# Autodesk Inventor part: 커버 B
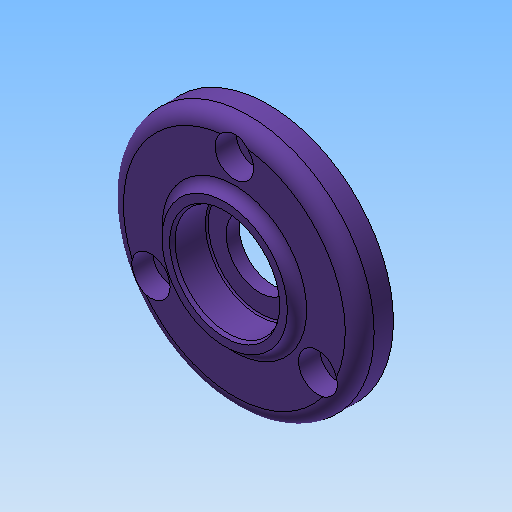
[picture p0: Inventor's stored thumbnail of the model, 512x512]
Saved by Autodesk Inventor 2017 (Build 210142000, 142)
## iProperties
Created: 2020-04
Part Number: 커버 B
Material: 알루미늄 6061
Document SubType Name: Modeling
Designer: mduedu
Density: 2.71 g/cm^3
Mass: 35.0669 g
Surface Area: 63.5386 cm^2
Volume: 12.9398 cm^3
Appearance: 보라색
Author: mduedu
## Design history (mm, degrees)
sketch "스케치1"
  geometry: C1 r 26 at (0, 0); 1 further point
  constraints: 1 centre point, 1 coincident
  dimensions: "d0" = 52 diameter of C1
extrude "돌출1" new body sketch "스케치1" distance "d1" = 7; taper "d2" = 0 deg
sketch "스케치6"
  geometry: C1 r 13 at (0, 0); 1 further point
  constraints: 1 centre point, 1 coincident
  dimensions: "d29" = 26 diameter of C1
extrude "돌출5" join sketch "스케치6" distance "d30" = 2; taper "d31" = 0 deg
fillet "모깎기2" dims "d7" = 3
fillet "모깎기4" dims "d33" = 2
sketch "스케치3" dims "d8" = 40
  geometry: 3 further points
  constraints: 2 vertical alignment, 1 coincident, 2 other
hole "구멍1" sketch "스케치3" at (0, 20) diameter "d9" = 4.5; stored, may be unused: countersink angle "d13" = 90 deg, drill point angle "d15" = 118 deg; dims "d10" = 6, "d11" = 8, "d12" = 4.4, "d14" = 8
sketch "스케치4"
  geometry: C1 r 14 at (0, 0); 1 further point
  constraints: 1 centre point, 1 coincident
  dimensions: "d19" = 28 diameter of C1
extrude "돌출3" join sketch "스케치4" distance "d20" = 4; taper "d21" = 0 deg
sketch "스케치5"
  geometry: C1 r 12 at (0, 0); 1 further point
  constraints: 1 centre point, 1 coincident
  dimensions: "d22" = 24 diameter of C1
extrude "돌출4" cut sketch "스케치5" distance "d23" = 3; taper "d24" = 0 deg
fillet "모깎기3" dims "d25" = 3
chamfer "모따기1" distance "d26" = 0.5; stored, may be unused: second distance "d27" = 2, angle "d28" = 45 deg
sketch "스케치7"
  geometry: 2 further points
  constraints: 1 coincident
hole "구멍2" sketch "스케치7" at (0, 0) diameter "d34" = 14; stored, may be unused: countersink angle "d38" = 90 deg, drill point angle "d40" = 118 deg; dims "d35" = 6, "d36" = 22, "d37" = 7.3, "d39" = 8
fillet "모깎기5" dims "d41" = 0.3
chamfer "모따기2" distance "d42" = 0.7; stored, may be unused: second distance "d43" = 2, angle "d44" = 30 deg
node "솔리드1"
pattern_circular "원형 패턴1" dims angle "d17" = 360 deg
